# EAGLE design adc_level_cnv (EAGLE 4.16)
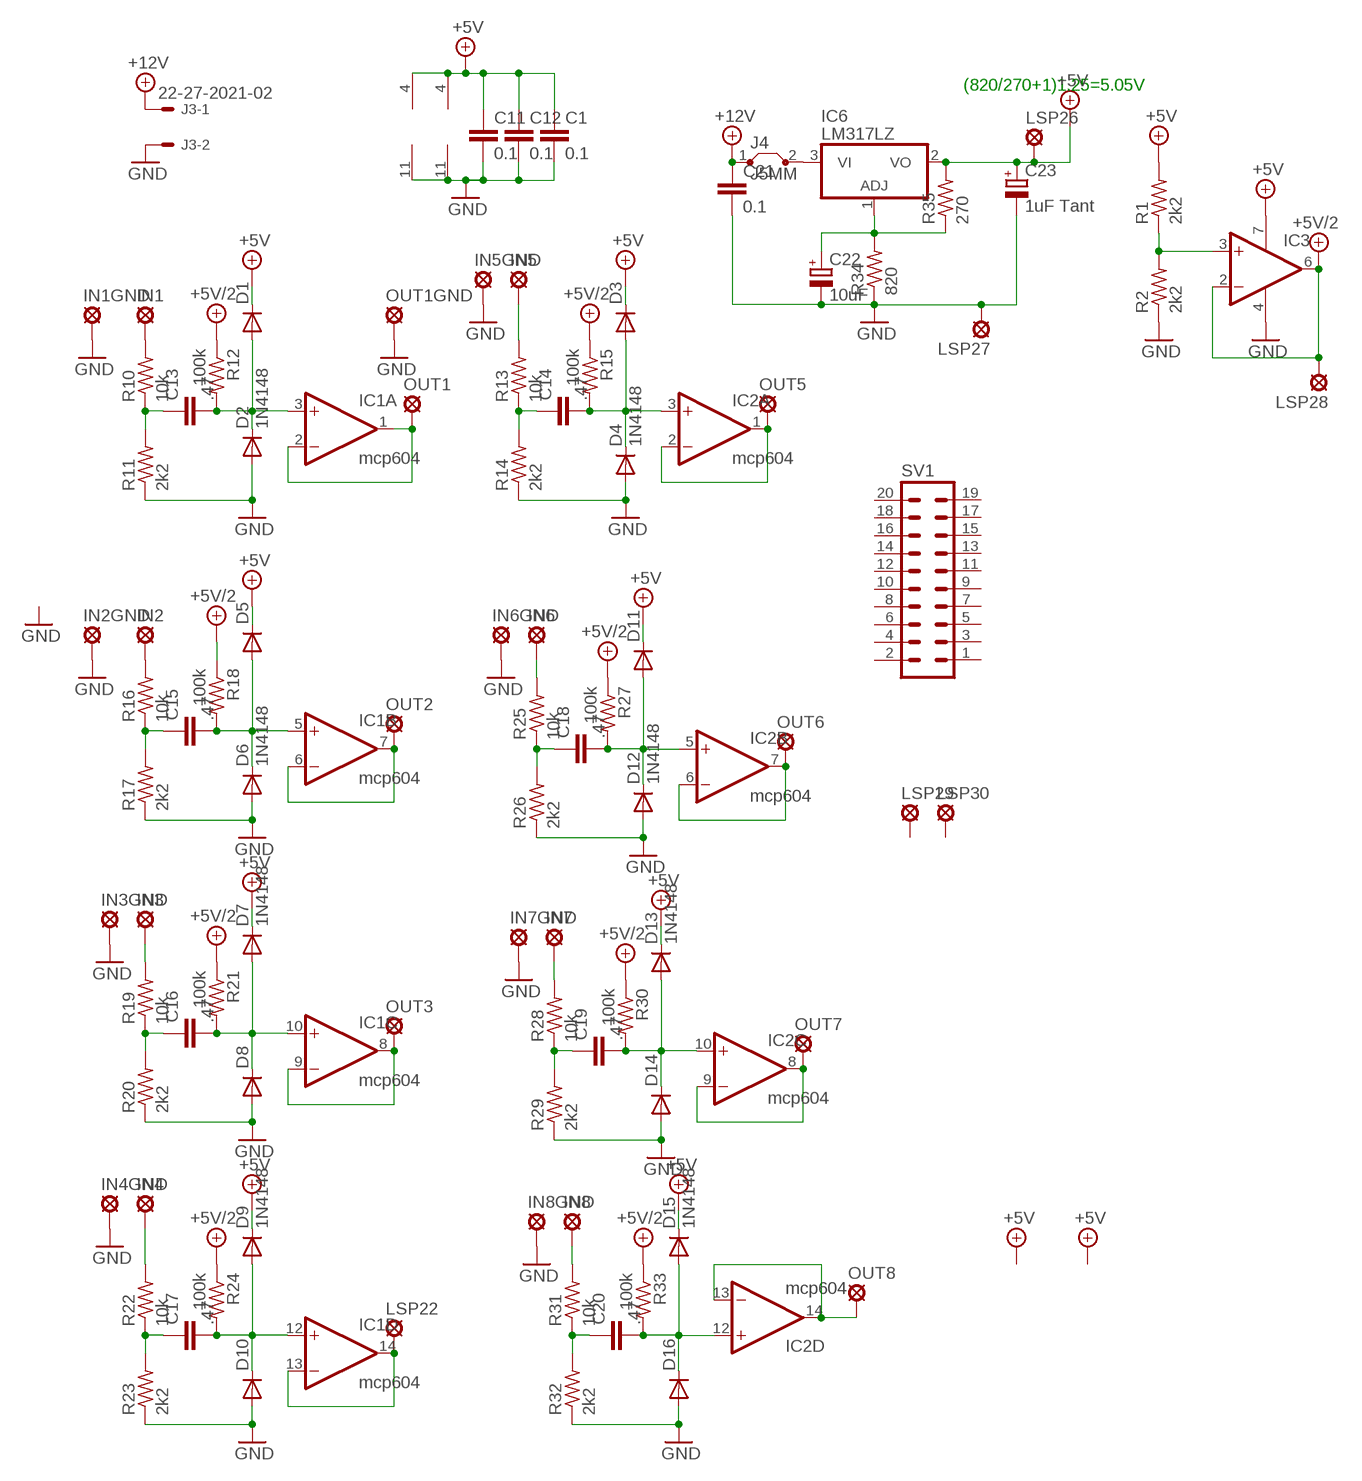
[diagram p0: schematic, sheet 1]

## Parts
C1  0.1  C-EU025-025X050  [C025-025X050]
C11  0.1  C-EUC1210  [C1210]
C12  0.1  C-EUC1210  [C1210]
C13  .47  C-EU050-025X075  [C050-025X075]
C14  .47  C-EU050-025X075  [C050-025X075]
C15  .47  C-EU025-025X050  [C025-025X050]
C16  .47  C-EU050-025X075  [C050-025X075]
C17  .47  C-EU050-025X075  [C050-025X075]
C18  .47  C-EU025-025X050  [C025-025X050]
C19  .47  C-EU050-025X075  [C050-025X075]
C20  .47  C-EU050-025X075  [C050-025X075]
C21  0.1  C-EU025-025X050  [C025-025X050]
C22  10uF  CPOL-EUTAP5-45  [TAP5-45]
C23  1uF Tant  CPOL-EUE2.5-4V  [E2,5RE]
D1  DIODE-D-2.5  [D-2.5]
D2  1N4148  [DO35-10]
D3  DIODE-D-2.5  [D-2.5]
D4  1N4148  [DO35-10]
D5  DIODE-D-2.5  [D-2.5]
D6  1N4148  [DO35-10]
D7  1N4148  [DO35-10]
D8  DIODE-D-2.5  [D-2.5]
D9  1N4148  [DO35-10]
D10  DIODE-D-2.5  [D-2.5]
D11  DIODE-D-2.5  [D-2.5]
D12  1N4148  [DO35-10]
D13  1N4148  [DO35-10]
D14  DIODE-D-2.5  [D-2.5]
D15  1N4148  [DO35-10]
D16  DIODE-D-2.5  [D-2.5]
IC1  mcp604  4AMP_P4+11N  [DIL14]
IC2  mcp604  4AMP_P4+11N  [DIL14]
IC3  1AMP_P7+4N  [DIL08]
IC6  LM317LZ  [TO92]
IN1  LSP10  [LSP10]
IN1GND  LSP10  [LSP10]
IN2  LSP10  [LSP10]
IN2GND  LSP10  [LSP10]
IN3  LSP10  [LSP10]
IN3GND  LSP10  [LSP10]
IN4  LSP10  [LSP10]
IN4GND  LSP10  [LSP10]
IN5  LSP10  [LSP10]
IN5GND  LSP10  [LSP10]
IN6  LSP10  [LSP10]
IN6GND  LSP10  [LSP10]
IN7  LSP10  [LSP10]
IN7GND  LSP10  [LSP10]
IN8  LSP10  [LSP10]
IN8GND  LSP10  [LSP10]
J3  22-27-2021-02  [6410-02]
J4  J5MM  [05]
LSP22  LSP10  [LSP10]
LSP26  LSP10  [LSP10]
LSP27  LSP10  [LSP10]
LSP28  LSP10  [LSP10]
LSP29  LSP10  [LSP10]
LSP30  LSP10  [LSP10]
OUT1  LSP10  [LSP10]
OUT1GND  LSP10  [LSP10]
OUT2  LSP10  [LSP10]
OUT3  LSP10  [LSP10]
OUT5  LSP10  [LSP10]
OUT6  LSP10  [LSP10]
OUT7  LSP10  [LSP10]
OUT8  LSP10  [LSP10]
R1  2k2  R-US_0207/10  [0207/10]
R2  2k2  R-US_0204/2V  [0204V]
R10  10k  R-US_0204/2V  [0204V]
R11  2k2  R-US_0204/5  [0204/5]
R12  100k  R-US_0204/5  [0204/5]
R13  10k  R-US_0204/2V  [0204V]
R14  2k2  R-US_0204/5  [0204/5]
R15  100k  R-US_0204/5  [0204/5]
R16  10k  R-US_0204/2V  [0204V]
R17  2k2  R-US_0204/5  [0204/5]
R18  100k  R-US_0204/5  [0204/5]
R19  10k  R-US_0204/7  [0204/7]
R20  2k2  R-US_0204/5  [0204/5]
R21  100k  R-US_0204/2V  [0204V]
R22  10k  R-US_0204/5  [0204/5]
R23  2k2  R-US_0204/5  [0204/5]
R24  100k  R-US_0204/2V  [0204V]
R25  10k  R-US_0204/2V  [0204V]
R26  2k2  R-US_0204/5  [0204/5]
R27  100k  R-US_0204/5  [0204/5]
R28  10k  R-US_0204/7  [0204/7]
R29  2k2  R-US_0204/5  [0204/5]
R30  100k  R-US_0204/2V  [0204V]
R31  10k  R-US_0204/5  [0204/5]
R32  2k2  R-US_0204/5  [0204/5]
R33  100k  R-US_0204/2V  [0204V]
R34  820  R-US_0204/5  [0204/5]
R35  270  R-US_0204/7  [0204/7]
SV1  MA10-2  [MA10-2]

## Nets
+5V [power]: C1.1 C11.1 C12.1 C23.+ D1.C D3.C D5.C D7.C D9.C D11.C D13.C D15.C IC1.4(P:V+) IC2.4(P:V+) IC3.7(V+) IC6.2(VO) LSP26.MP R1.2 R35.2
+5V/2 [+05V/2]: IC3.2(-IN) IC3.6(OUT) LSP28.MP R12.1 R15.1 R18.1 R21.1 R24.1 R27.1 R30.1 R33.1
+12V [power]: C21.1 J3.1 J4.1
AN0: IC1.1(A:OUT) IC1.2(A:-IN) OUT1.MP
AN1: IC1.13(D:-IN) IC1.14(D:OUT) LSP22.MP
AN2: IC1.6(B:-IN) IC1.7(B:OUT) OUT2.MP
AN3: IC1.8(C:OUT) IC1.9(C:-IN) OUT3.MP
AN4: IC2.1(A:OUT) IC2.2(A:-IN) OUT5.MP
AN5: IC2.13(D:-IN) IC2.14(D:OUT) OUT8.MP
AN6: IC2.6(B:-IN) IC2.7(B:OUT) OUT6.MP
AN7: IC2.8(C:OUT) IC2.9(C:-IN) OUT7.MP
ANI2: IN5.MP R13.2
ANI3: IN6.MP R25.2
ANI4: IN4.MP R22.2
ANI5: IN3.MP R19.2
ANI6: IN8.MP R31.2
ANI7: IN7.MP R28.2
GND [power]: C1.2 C11.2 C12.2 C21.2 C22.- C23.- D2.A D4.A D6.A D8.A D10.A D12.A D14.A D16.A IC1.11(P:V-) IC2.11(P:V-) IC3.4(V-) IN1GND.MP IN2GND.MP IN3GND.MP IN4GND.MP IN5GND.MP IN6GND.MP IN7GND.MP IN8GND.MP J3.2 LSP27.MP OUT1GND.MP R2.1 R11.1 R14.1 R17.1 R20.1 R23.1 R26.1 R29.1 R32.1 R34.1
N$1: IC6.3(VI) J4.2
N$2: IC3.3(+IN) R1.1 R2.2
N$3: IN1.MP R10.2
N$4: IN2.MP R16.2
N$11: C13.1 R10.1 R11.2
N$12: C13.2 D1.A D2.C IC1.3(A:+IN) R12.2
N$15: C14.1 R13.1 R14.2
N$16: C14.2 D3.A D4.C IC2.3(A:+IN) R15.2
N$18: C15.1 R16.1 R17.2
N$19: C15.2 D5.A D6.C IC1.5(B:+IN) R18.2
N$21: C16.1 R19.1 R20.2
N$22: C16.2 D7.A D8.C IC1.10(C:+IN) R21.2
N$24: C17.1 R22.1 R23.2
N$25: C17.2 D9.A D10.C IC1.12(D:+IN) R24.2
N$27: C18.1 R25.1 R26.2
N$28: C18.2 D11.A D12.C IC2.5(B:+IN) R27.2
N$30: C19.1 R28.1 R29.2
N$31: C19.2 D13.A D14.C IC2.10(C:+IN) R30.2
N$33: C20.1 R31.1 R32.2
N$34: C20.2 D15.A D16.C IC2.12(D:+IN) R33.2
N$39: C22.+ IC6.1(ADJ) R34.2 R35.1
Unconnected: LSP29.MP LSP30.MP SV1.1 SV1.2 SV1.3 SV1.4 SV1.5 SV1.6 SV1.7 SV1.8 SV1.9 SV1.10 SV1.11 SV1.12 SV1.13 SV1.14 SV1.15 SV1.16 SV1.17 SV1.18 SV1.19 SV1.20

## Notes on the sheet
- (820/270+1)1.25=5.05V

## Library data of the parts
C1 C11-C21 = rcl:C-EU: CAPACITOR, European symbol
C22 C23 = rcl:CPOL-EU: POLARIZED CAPACITOR, European symbol
D1 D3 D5 D8 D10 D11 D14 D16 = diode:DIODE-: DIODE
D2 D4 D6 D7 D9 D12 D13 D15 = diode:1N4148: DIODE
IC1 IC2 = linear:4AMP_P4+11: OP AMP
IC3 = linear:1AMP_P7+4: OP AMP
IC6 = linear:*317: Positive VOLTAGE REGULATOR
IN1 IN1GND IN2 IN2GND IN3 IN3GND IN4 IN4GND IN5 IN5GND IN6 IN6GND IN7 IN7GND IN8 IN8GND LSP22 LSP26-LSP30 OUT1 OUT1GND OUT2 OUT3 OUT5-OUT8 = solpad:LSP10: SOLDER PAD
J3 = con-molex:22-?-02: CONNECTOR
J4 = jumper:J: Bridge
R1 R2 R10-R35 = rcl:R-US_: RESISTOR, American symbol
SV1 = con-lstb:MA10-2: PIN HEADER

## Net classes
0 default: width 0.61 mm, drill 0.254 mm, clearance 0.711 mm
1 power: width 0.61 mm, drill 0.305 mm, clearance 0.711 mm
2 +05V/2: width 0.61 mm, drill 0.254 mm, clearance 0.711 mm

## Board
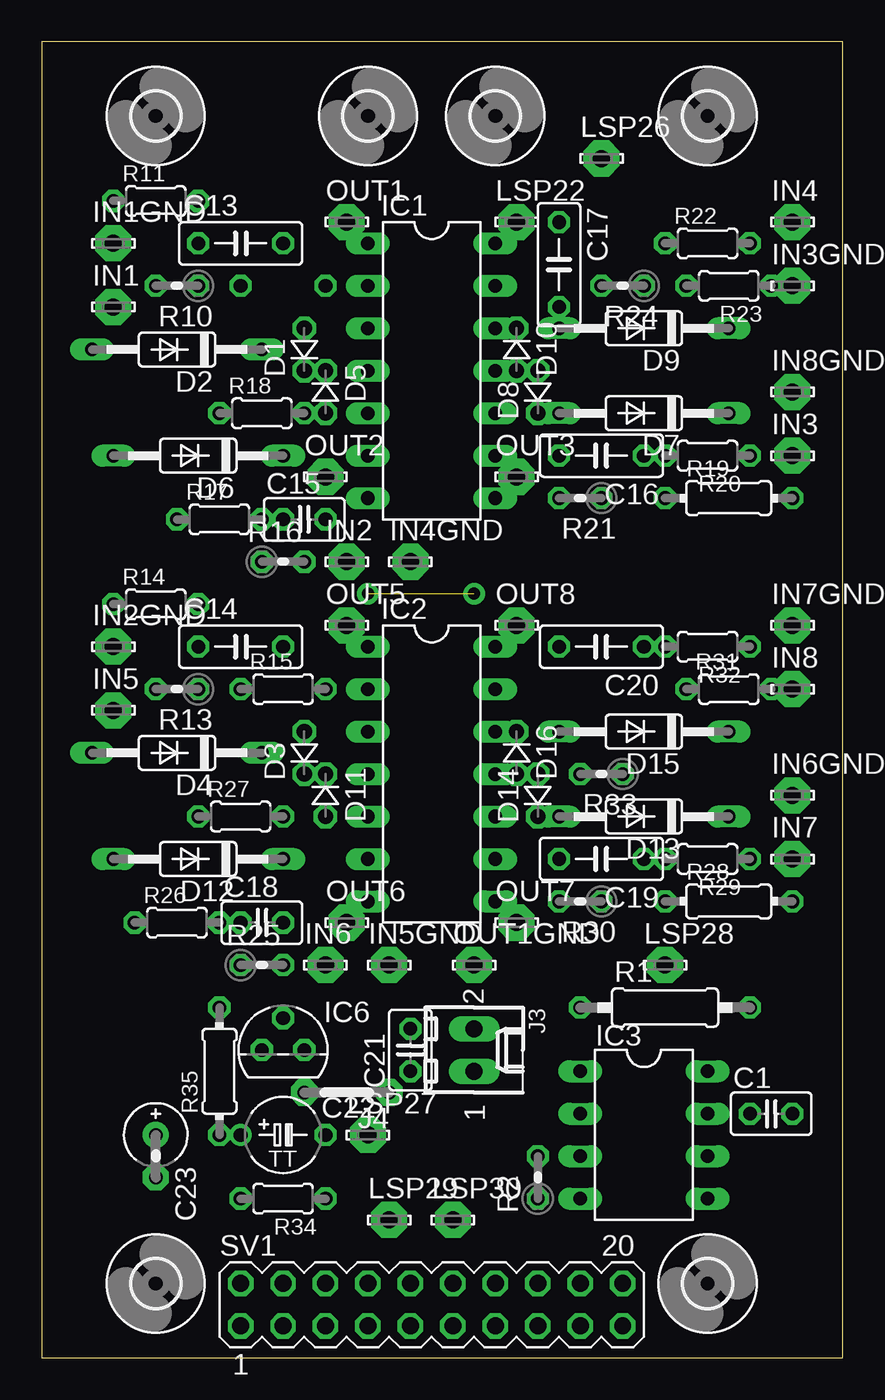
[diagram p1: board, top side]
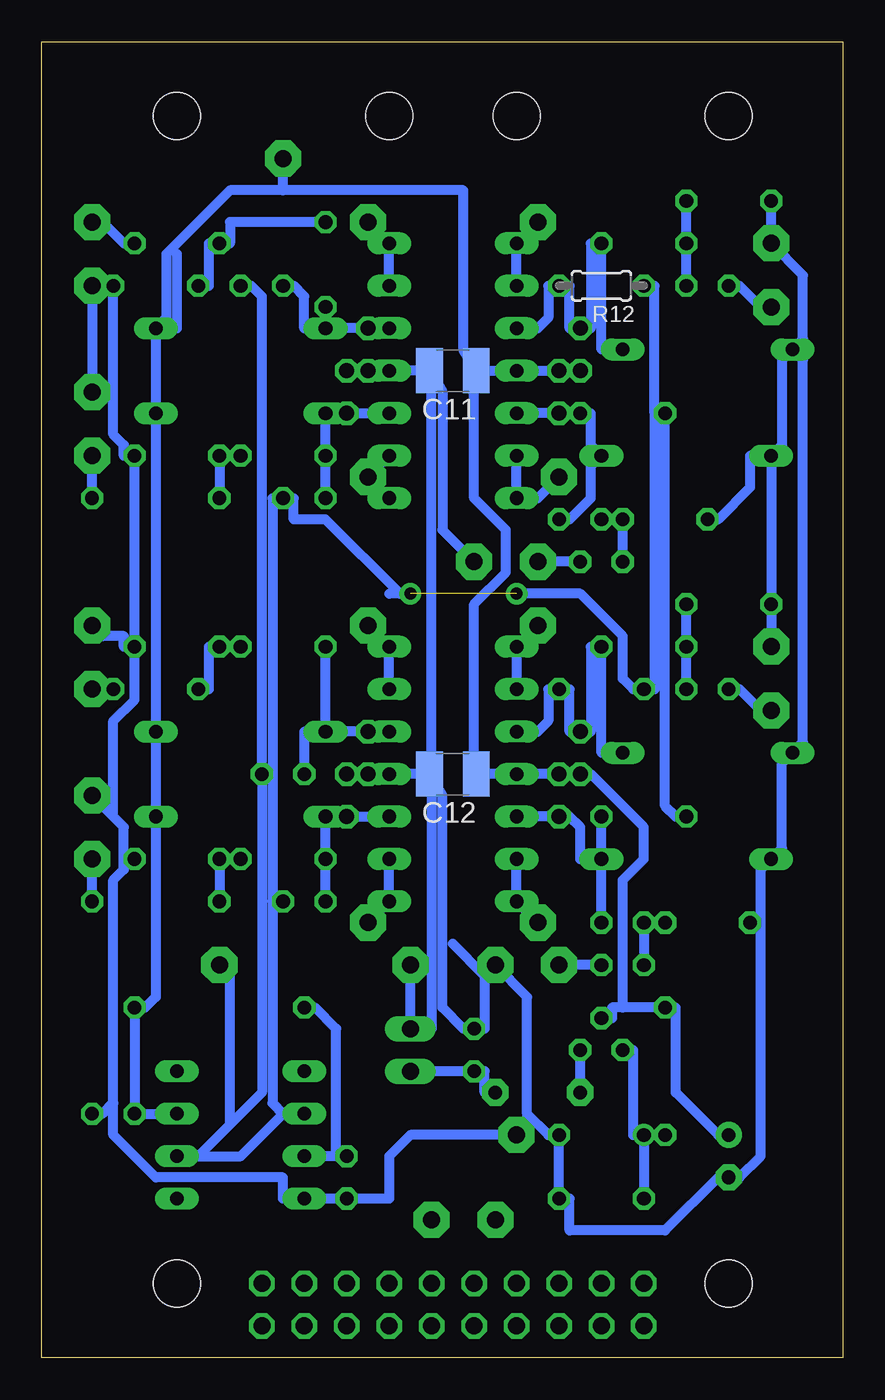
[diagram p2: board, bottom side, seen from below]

Size 47.93 x 78.73 mm. Coordinates in mm from the lower left corner, seen from the top.
Outline: 0,0 47.93,0 47.93,78.73 0,78.73 0,0
Copper layers (1*16): Top 0.035mm / dielectric 1.5mm / Bottom 0.035mm
Design rules "futurlec": minimum track width 10mil, minimum drill 24mil, track to track 10mil, track to pad 10mil, pad to pad 10mil, via to via 10mil, smd to smd 0mil, copper to edge 40mil, drill to drill 10mil, minimum pad ring 10mil, minimum via ring 8mil, stop-mask expansion 4mil, vias tented up to drill 0mil, thermal gap 10mil

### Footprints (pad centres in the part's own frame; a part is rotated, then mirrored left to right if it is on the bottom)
C025-025X050 = drill 0.813 octagon: 1 -1.27,0; 2 1.27,0
C1210 = smd 1.6 x 2.7: 1 -1.4,0; 2 1.4,0
C050-025X075 = drill 0.813 octagon: 1 -2.54,0; 2 2.54,0
TAP5-45 = drill 0.813 round: + -2.54,0 | drill 0.813 octagon: - 2.54,0
E2,5RE = drill 0.813 pad 1.575 round: + -1.27,0 | drill 0.813 pad 1.575 octagon: - 1.27,0
D-2.5 = drill 0.9 octagon: A 1.27,0; C -1.27,0
DO35-10 = drill 0.813 long: A 5.08,0; C -5.08,0
DIL14 = drill 0.813 long: 1 -7.62,-3.81; 2 -5.08,-3.81; 3 -2.54,-3.81; 4 0,-3.81; 5 2.54,-3.81; 6 5.08,-3.81; 7 7.62,-3.81; 8 7.62,3.81; 9 5.08,3.81; 10 2.54,3.81; 11 0,3.81; 12 -2.54,3.81; 13 -5.08,3.81; 14 -7.62,3.81
DIL08 = drill 0.813 long: 1 -3.81,-3.81; 2 -1.27,-3.81; 3 1.27,-3.81; 4 3.81,-3.81; 5 3.81,3.81; 6 1.27,3.81; 7 -1.27,3.81; 8 -3.81,3.81
TO92 = drill 0.813 octagon: 1 -1.27,0; 2 0,1.905; 3 1.27,0
LSP10 = drill 1.016 pad 2.159 octagon: MP 0,0
6410-02 = drill 1.016 long: 1 1.27,0; 2 -1.27,0
05 = drill 0.813 pad 1.6 octagon: 1 -2.54,0; 2 2.54,0
0207/10 = drill 0.813 octagon: 1 -5.08,0; 2 5.08,0
0204V = drill 0.813 octagon: 1 -1.27,0; 2 1.27,0
0204/5 = drill 0.813 octagon: 1 -2.54,0; 2 2.54,0
0204/7 = drill 0.813 octagon: 1 -3.81,0; 2 3.81,0
MA10-2 = drill 1.016 octagon: 1 -11.43,-1.27; 2 -11.43,1.27; 3 -8.89,-1.27; 4 -8.89,1.27; 5 -6.35,-1.27; 6 -6.35,1.27; 7 -3.81,-1.27; 8 -3.81,1.27; 9 -1.27,-1.27; 10 -1.27,1.27; 11 1.27,-1.27; 12 1.27,1.27; 13 3.81,-1.27; 14 3.81,1.27; 15 6.35,-1.27; 16 6.35,1.27; 17 8.89,-1.27; 18 8.89,1.27; 19 11.43,-1.27; 20 11.43,1.27
2,8 = hole 2.8: 0,0

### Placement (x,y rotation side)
C1  43.65,14.6 0 top
C11  23.33,59.05 180 bottom
C12  23.33,34.92 180 bottom
C13  11.9,66.67 0 top
C14  11.9,42.54 0 top
C15  15.71,50.16 0 top
C16  33.49,53.97 180 top
C17  30.95,65.4 270 top
C18  13.17,26.03 0 top
C19  33.49,29.84 180 top
C20  33.49,42.54 180 top
C21  22.06,18.41 90 top
C22  14.44,13.33 0 top
C23  6.82,12.06 270 top
D1  15.71,60.32 90 top
D2  8.09,60.32 180 top
D3  15.71,36.19 90 top
D4  8.09,36.19 180 top
D5  16.98,57.78 270 top
D6  9.36,53.97 180 top
D7  36.03,56.51 180 top
D8  29.68,57.78 90 top
D9  36.03,61.59 180 top
D10  28.41,60.32 270 top
D11  16.98,33.65 270 top
D12  9.36,29.84 180 top
D13  36.03,32.38 180 top
D14  29.68,33.65 90 top
D15  36.03,37.46 180 top
D16  28.41,36.19 270 top
IC1  23.33,59.05 270 top
IC2  23.33,34.92 270 top
IC3  36.03,13.33 270 top
IC6  14.44,18.41 0 top
IN1  4.28,62.86 0 top
IN1GND  4.28,66.67 0 top
IN2  18.25,47.62 0 top
IN2GND  4.28,42.54 0 top
IN3  44.92,53.97 0 top
IN3GND  44.92,64.13 0 top
IN4  44.92,67.94 0 top
IN4GND  22.06,47.62 0 top
IN5  4.28,38.73 0 top
IN5GND  20.79,23.49 0 top
IN6  16.98,23.49 0 top
IN6GND  44.92,33.65 0 top
IN7  44.92,29.84 0 top
IN7GND  44.92,43.81 0 top
IN8  44.92,40 0 top
IN8GND  44.92,57.78 0 top
J3  25.87,18.41 270 top
J4  18.25,15.87 180 top
LSP22  28.41,67.94 0 top
LSP26  33.49,71.75 0 top
LSP27  19.52,13.33 0 top
LSP28  37.3,23.49 0 top
LSP29  20.79,8.25 0 top
LSP30  24.6,8.25 0 top
OUT1  18.25,67.94 0 top
OUT1GND  25.87,23.49 0 top
OUT2  16.98,52.7 0 top
OUT3  28.41,52.7 0 top
OUT5  18.25,43.81 0 top
OUT6  18.25,26.03 0 top
OUT7  28.41,26.03 0 top
OUT8  28.41,43.81 0 top
R1  37.3,20.95 0 top
R2  29.68,10.79 90 top
R10  8.09,64.13 180 top
R11  6.82,69.21 0 top
R12  14.44,64.13 180 bottom
R13  8.09,40 180 top
R14  6.82,45.08 0 top
R15  14.44,40 0 top
R16  14.44,47.62 0 top
R17  10.63,50.16 0 top
R18  13.17,56.51 0 top
R19  41.11,51.43 0 top
R20  39.84,53.97 180 top
R21  32.22,51.43 180 top
R22  39.84,66.67 0 top
R23  41.11,64.13 180 top
R24  34.76,64.13 180 top
R25  13.17,23.49 0 top
R26  8.09,26.03 0 top
R27  11.9,32.38 0 top
R28  41.11,27.3 0 top
R29  39.84,29.84 180 top
R30  32.22,27.3 180 top
R31  41.11,40 0 top
R32  39.84,42.54 180 top
R33  33.49,34.92 180 top
R34  14.44,9.52 180 top
R35  10.63,17.14 90 top
SV1  23.33,3.17 0 top
U$1  [2,8]  39.84,74.29 0 top
U$2  [2,8]  39.84,4.44 0 top
U$3  [2,8]  6.82,4.44 0 top
U$4  [2,8]  6.82,74.29 0 top
U$5  [2,8]  19.52,74.29 0 top
U$6  [2,8]  27.14,74.29 0 top

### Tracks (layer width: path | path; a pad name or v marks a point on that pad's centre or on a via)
+5V
  Bottom 0.61: IC3.7 C1.1 R1.2 41.75,20.95 41.11,21.59 D13.C D15.C D7.C D9.C | 13.17,20.95 13.8,20.95 13.8,20.32 IC6.2 | 13.17,20.95 R35.2 10,20.95 10,15.87 7.46,13.33 C23.+ | D1.C D5.C IC1.4 C11.1 | C11.1 22.06,57.78 22.06,51.43 20.16,49.52 20.16,46.98 22.06,45.08 22.06,36.19 C12.1 IC2.4 D11.C D3.C 15.07,34.92 11.9,31.74 11.9,29.84 13.17,28.57 13.17,20.95 | 39.84,66.03 39.84,61.59 D9.C | 33.49,69.84 22.7,69.84 22.7,60.32 C11.1 | 33.49,69.84 LSP26.MP | 33.49,69.84 36.67,69.84 40.47,66.03 40.47,62.23 D9.C
+5V/2  (via drill 0.71)  (1 unrouted)
  Bottom 0.61: R27.1 10,32.38 10.63,33.02 R18.1 11.27,56.51 | 11.27,56.51 11.27,40 R15.1 12.54,40 13.17,40.63 13.17,43.17 15.71,45.72 v19.52,45.72 | 11.27,56.51 11.27,64.13 R12.1 | 33.49,14.6 34.12,15.23 34.12,27.3 | 33.49,14.6 IC3.2 | 34.12,34.92 34.12,51.43 R21.1 32.86,51.43 32.86,50.16 30.95,50.16 26.5,45.72 | R24.1 35.39,64.13 34.76,63.49 R33.1 | 36.67,13.96 34.76,15.87 R33.1 | 36.67,13.96 38.57,12.06 | 38.57,12.06 IC3.6 | 34.12,34.92 34.12,27.3 | 34.12,27.3 R30.1 | 34.12,34.92 R33.1 | 36.67,13.96 36.67,22.86 LSP28.MP | 38.57,12.06 36.03,12.06 33.49,14.6 | 26.5,45.72 27.14,45.72 | v25.87,45.72 26.5,45.72
+12V
  Bottom 0.61: J4.1 21.43,15.87 21.43,17.14 C21.1 J3.1
AN0
  Bottom 0.61: IC1.2 IC1.1 OUT1.MP
AN1
  Bottom 0.61: IC1.13 IC1.14 LSP22.MP
AN2
  Bottom 0.61: IC1.6 IC1.7 18.25,51.43 OUT2.MP
AN3
  Bottom 0.61: IC1.8 OUT3.MP IC1.9
AN4
  Bottom 0.61: IC2.2 IC2.1 OUT5.MP
AN5
  Bottom 0.61: IC2.13 IC2.14 OUT8.MP
AN6
  Bottom 0.61: OUT6.MP IC2.7 IC2.6
AN7
  Bottom 0.61: OUT7.MP IC2.8 IC2.9
ANI2
  Bottom 0.61: R13.2 6.19,40 4.92,38.73 IN5.MP
ANI3
  Bottom 0.61: R25.2 IN6.MP
ANI4
  Bottom 0.61: R22.2 43.02,66.67 44.28,67.94 IN4.MP
ANI5
  Bottom 0.61: R19.2 IN3.MP
ANI6
  Bottom 0.61: R31.2 IN8.MP
ANI7
  Bottom 0.61: R28.2 IN7.MP
GND
  Bottom 0.61: 4.92,26.03 4.92,29.2 D12.A 3.65,30.48 3.65,35.55 D4.A 2.38,36.83 2.38,59.69 D2.A | 4.92,26.03 4.92,12.06 6.19,10.79 C23.- 7.46,10.79 10.63,7.62 16.34,7.62 16.34,9.52 R34.1 C22.- 17.61,13.33 18.89,14.6 | 4.92,26.03 R26.1 | R11.1 IN1GND.MP 2.38,64.76 2.38,60.96 D2.A | IN2GND.MP R14.1 D6.A | D6.A 3.65,54.6 3.65,59.69 D2.A | R17.1 7.46,50.16 5.55,52.06 5.55,53.97 D6.A | 43.02,29.84 43.02,31.74 43.65,32.38 | 43.65,32.38 IN6GND.MP | 43.65,15.23 44.28,14.6 C1.2 | 43.65,15.23 43.65,28.57 43.02,29.2 43.02,29.84 | 43.02,29.84 R29.1 | IN8GND.MP IN3GND.MP R23.1 43.65,55.24 43.02,54.6 43.02,53.97 R20.1 R32.1 | IN7GND.MP 44.28,43.17 43.02,43.17 43.02,42.54 R32.1 | 43.65,32.38 43.65,38.09 42.38,39.37 R32.1 | 21.43,22.86 21.43,19.68 C21.2 22.7,19.68 23.96,20.95 23.96,33.65 C12.2 | 18.89,14.6 18.89,21.59 IN5GND.MP 21.43,22.86 | D8.A D10.A IC1.11 C11.2 | D14.A D16.A IC2.11 C12.2 | C12.2 24.6,33.65 24.6,19.68 J3.2 OUT1GND.MP | C11.2 24.6,57.78 24.6,36.19 C12.2 | IN4GND.MP 23.96,49.52 23.96,57.78 C11.2 | 43.65,15.23 43.65,13.33 41.11,10.79 33.49,10.79 33.49,9.52 IC3.4 R2.1 27.14,9.52 27.14,12.06 25.87,13.33 LSP27.MP 18.89,13.96 18.89,14.6 | 21.43,22.86 23.33,24.76
N$1
  Bottom 0.61: J4.2 IC6.3
N$2
  Bottom 0.61: R2.2 30.32,12.06 | 30.32,12.06 IC3.3 | 30.32,12.06 30.32,19.68 31.58,20.95 R1.1
N$3
  Bottom 0.61: R10.2 6.19,64.13 4.92,62.86 IN1.MP
N$4
  Bottom 0.61: R16.2 IN2.MP
N$11
  Bottom 0.61: R10.1 C13.1 R11.2
N$12
  Bottom 0.61: IC1.3 18.25,61.59 17.61,62.23 17.61,64.13 R12.2 16.34,64.13 16.34,61.59 D1.A 15.07,61.59 15.07,66.67 C13.2 14.44,60.32 D2.C
N$15
  Bottom 0.61: R13.1 C14.1 R14.2
N$16
  Bottom 0.61: IC2.3 18.25,37.46 17.61,38.09 17.61,40 R15.2 16.34,40 16.34,37.46 D3.A 15.07,37.46 15.07,42.54 C14.2 14.44,36.19 D4.C
N$18
  Bottom 0.61: R16.1 R17.2 C15.1
N$19
  Bottom 0.61: IC1.5 D5.A R18.2 15.07,56.51 15.07,54.6 D6.C 15.07,53.34 15.07,51.43 16.34,50.16 C15.2
N$21
  Bottom 0.61: C16.1 R20.2 R19.1
N$22
  Bottom 0.61: R21.2 C16.2 D7.A D8.C IC1.10
N$24
  Bottom 0.61: R23.2 37.94,64.13 37.94,66.67 R22.1 36.67,66.67 36.67,67.94 C17.1
N$25
  Bottom 0.61: IC1.12 D10.C D9.A | D9.A C17.2 | R24.2 32.86,64.13 32.22,63.49 32.22,61.59 D9.A
N$27
  Bottom 0.61: R26.2 C18.1 R25.1
N$28
  Bottom 0.61: IC2.5 D11.A 16.34,32.38 15.71,31.74 15.71,29.84 D12.C | C18.2 D12.C | D12.C R27.2
N$30
  Bottom 0.61: C19.1 R29.2 R28.1
N$31
  Bottom 0.61: R30.2 C19.2 D13.A D14.C IC2.10
N$33
  Bottom 0.61: C20.1 R32.2 37.94,42.54 37.94,40 R31.1
N$34
  Bottom 0.61: IC2.12 D16.C D15.A | D15.A 32.22,37.46 R33.2 | D15.A C20.2
N$39
  Bottom 0.61: R35.1 C22.+ | C22.+ R34.2 | IC6.1 12.54,18.41 12.54,13.33 C22.+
